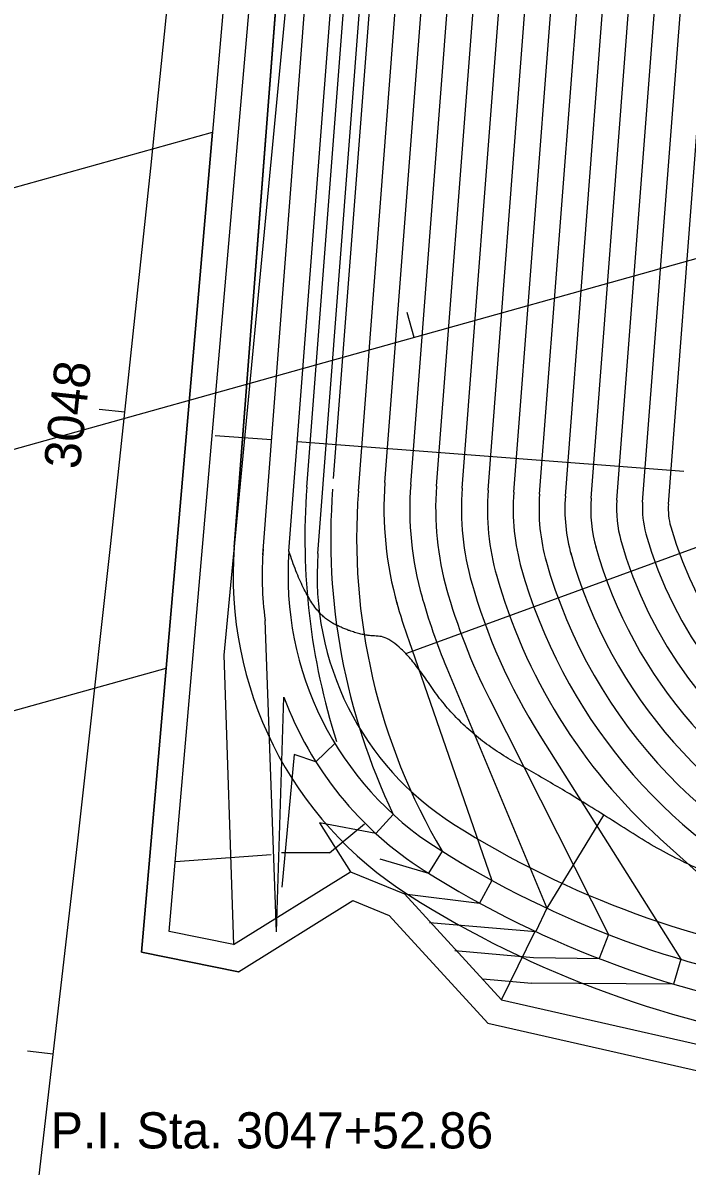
# Model space of a CAD drawing. Extents: x 1512289 to 1544686, y 552531 to 589211.
# Drawn here: x 1543224.9 to 1543276.3, y 587330.8 to 587419.3 of the extents above; entities that cross this region are included whole.
import ezdxf

# ---------------------------------------------------------------- set-up
doc = ezdxf.new("R2010")
doc.units = 0
for name, color, linetype in [('DR_P_Ditch', 7, 'Continuous'), ('DR_P_Erosion_Control', 7, 'Continuous'), ('DT_P_Break_Line', 7, 'Continuous'), ('DT_P_Contour_Major', 7, 'Continuous'), ('DT_P_Contour_Minor', 7, 'Continuous'), ('DT_P_Slope_Break_Line', 7, 'Continuous'), ('DT_P_TIN_Hull', 7, 'Continuous'), ('GE_X_CL_20', 7, 'Continuous'), ('GK_Visualization', 7, 'Continuous'), ('RW_P_Const_Limits', 7, 'Continuous'), ('SC_Scratch2', 7, 'Continuous')]:
    doc.layers.add(name, color=color, linetype=linetype)

msp = doc.modelspace()

# ---------------------------------------------------------------- linework, layer by layer
at = {"layer": 'DR_P_Ditch'}
for p, q in [((1543243.419, 587378.158), (1543246.948, 587424.142)), ((1543245.446, 587378.435), (1543248.942, 587423.989)), ((1543244.47, 587348.981), (1543243.593, 587373.077)), ((1543244.47, 587348.981), (1543245.06, 587367.128))]:
    msp.add_line(p, q, dxfattribs=at)
for centre, radius, start, end in [((1543270.373, 587376.522), 27, 175.61111, 187.3289), ((1543270.373, 587376.522), 25, 175.61111, 237.61296), ((1543270.373, 587376.522), 27, 200.36085, 237.61296), ((1543297.316, 587418.999), 75.302, 237.61296, 262.3082), ((1543297.316, 587418.999), 77.302, 237.61296, 262.3082)]:
    msp.add_arc(centre, radius, start, end, dxfattribs=at)
at = {"layer": 'DR_P_Erosion_Control'}
for p, q in [((1543241.209, 587378.76), (1543244.705, 587424.314)), ((1543244.705, 587424.314), (1543241.209, 587378.76)), ((1543247.69, 587378.263), (1543251.186, 587423.817)), ((1543247.69, 587378.263), (1543251.186, 587423.817))]:
    msp.add_line(p, q, dxfattribs=at)
for centre, radius, start, end in [((1543270.373, 587376.522), 29.25, 175.61111, 237.61296), ((1543270.373, 587376.522), 29.25, 175.61111, 237.61296), ((1543270.373, 587376.522), 22.75, 175.61111, 237.61296), ((1543270.373, 587376.522), 22.75, 175.61111, 237.61296), ((1543297.316, 587418.999), 73.052, 237.61296, 262.3082), ((1543297.316, 587418.999), 73.052, 237.61296, 262.3082), ((1543297.316, 587418.999), 79.552, 237.61296, 262.3082), ((1543297.316, 587418.999), 79.552, 237.61296, 262.3082)]:
    msp.add_arc(centre, radius, start, end, dxfattribs=at)
at = {"layer": 'DT_P_Break_Line'}
msp.add_line((1543241.154, 587347.996), (1543236.172, 587349), dxfattribs=at)
msp.add_lwpolyline([(1543241.154, 587347.996), (1543250.205, 587353.624), (1543254.38, 587351.91), (1543261.898, 587343.717), (1543284.879, 587338.499)], dxfattribs=at)
msp.add_open_spline([(1543307.516, 587355.279), (1543303.761, 587353.574), (1543297.723, 587353.574), (1543296.29, 587352.959), (1543290.972, 587350.957), (1543286.569, 587350.488), (1543276.224, 587353.875), (1543267.091, 587359.788), (1543258.853, 587364.356), (1543253.82, 587371.866), (1543250.743, 587371.866), (1543246.919, 587373.852), (1543245.446, 587378.435)], degree=2, dxfattribs=at)
at = {"layer": 'DT_P_Contour_Major'}
for p, q in [((1543252.876, 587383.764), (1543255.922, 587423.454)), ((1543262.846, 587382.999), (1543265.893, 587422.688)), ((1543272.817, 587382.234), (1543275.863, 587421.923)), ((1543254.71, 587371.511), (1543261.155, 587352.948)), ((1543261.155, 587352.948), (1543260.195, 587351.194)), ((1543254.38, 587351.91), (1543260.195, 587351.194))]:
    msp.add_line(p, q, dxfattribs=at)
for centre, radius, start, end in [((1543279.797, 587381.698), 27, 175.61111, 195.86297), ((1543279.797, 587381.698), 17, 175.61111, 195.86297), ((1543279.797, 587381.698), 7, 175.61111, 195.86297), ((1543303.222, 587388.354), 31.353, 195.86297, 279.22466), ((1543303.222, 587388.354), 41.353, 195.61111, 243.74464), ((1543303.222, 587388.354), 51.353, 195.61111, 199.14743)]:
    msp.add_arc(centre, radius, start, end, dxfattribs=at)
at = {"layer": 'DT_P_Contour_Minor'}
for p, q in [((1543247.421, 587443.908), (1543240.411, 587370.396)), ((1543246.829, 587383.384), (1543249.94, 587423.913)), ((1543248.887, 587384.07), (1543251.934, 587423.76)), ((1543250.817, 587383.078), (1543253.928, 587423.607)), ((1543254.87, 587383.611), (1543257.916, 587423.301)), ((1543256.864, 587383.458), (1543259.91, 587423.147)), ((1543258.858, 587383.305), (1543261.904, 587422.994)), ((1543260.852, 587383.152), (1543263.898, 587422.841)), ((1543264.841, 587382.846), (1543267.887, 587422.535)), ((1543266.835, 587382.693), (1543269.881, 587422.382)), ((1543268.829, 587382.54), (1543271.875, 587422.229)), ((1543270.823, 587382.387), (1543273.869, 587422.076)), ((1543274.811, 587382.08), (1543277.857, 587421.77)), ((1543240.411, 587370.396), (1543241.154, 587347.996)), ((1543257.658, 587369.391), (1543265.396, 587350.797)), ((1543260.954, 587367.006), (1543270.17, 587348.761)), ((1543264.85, 587364.179), (1543275.77, 587346.846)), ((1543249.007, 587363.541), (1543247.536, 587362.117)), ((1543245.848, 587362.686), (1543244.902, 587352.427)), ((1543247.536, 587362.117), (1543245.848, 587362.686)), ((1543253.519, 587358.056), (1543252.171, 587356.579)), ((1543252.171, 587356.579), (1543247.811, 587357.403)), ((1543247.811, 587357.403), (1543250.205, 587353.624)), ((1543274.166, 587356.18), (1543287.237, 587344.375)), ((1543257.301, 587355.209), (1543256.256, 587353.506)), ((1543252.484, 587354.614), (1543256.256, 587353.506)), ((1543265.396, 587350.797), (1543264.549, 587348.986)), ((1543256.334, 587349.687), (1543264.549, 587348.986)), ((1543270.17, 587348.761), (1543269.449, 587346.895)), ((1543258.293, 587347.512), (1543264.379, 587346.993)), ((1543264.379, 587346.993), (1543269.449, 587346.895)), ((1543275.77, 587346.846), (1543275.198, 587344.929)), ((1543260.451, 587345.321), (1543264.208, 587345)), ((1543275.198, 587344.929), (1543264.208, 587345))]:
    msp.add_line(p, q, dxfattribs=at)
for centre, radius, start, end in [((1543298.29, 587379.434), 51.613, 175.61111, 197.74433), ((1543298.29, 587379.434), 49.613, 175.61111, 205.52395), ((1543279.797, 587381.698), 25, 175.61111, 195.86297), ((1543279.797, 587381.698), 23, 175.61111, 195.86297), ((1543279.797, 587381.698), 21, 175.61111, 195.86297), ((1543298.29, 587379.434), 47.613, 175.61111, 210.58297), ((1543279.797, 587381.698), 19, 175.61111, 195.86297), ((1543279.797, 587381.698), 15, 175.61111, 195.86297), ((1543279.797, 587381.698), 13, 175.61111, 195.86297), ((1543279.797, 587381.698), 11, 175.61111, 195.86297), ((1543279.797, 587381.698), 9, 175.61111, 195.86297), ((1543279.797, 587381.698), 5, 175.61111, 195.86297), ((1543303.222, 587388.354), 29.353, 195.86297, 281.26542), ((1543303.222, 587388.354), 35.353, 195.61111, 246.82613), ((1543303.222, 587388.354), 33.353, 195.61111, 277.39562), ((1543303.222, 587388.354), 37.353, 195.61111, 247.2377), ((1543303.222, 587388.354), 39.353, 195.61111, 251.86284), ((1543303.222, 587388.354), 45.353, 195.61111, 212.21141), ((1543303.222, 587388.354), 43.353, 195.61111, 227.91501), ((1543303.222, 587388.354), 47.353, 195.61111, 206.79697), ((1543303.222, 587388.354), 49.353, 195.61111, 202.59672)]:
    msp.add_arc(centre, radius, start, end, dxfattribs=at)
at = {"layer": 'DT_P_Slope_Break_Line'}
for p, q in [((1543239.739, 587387.397), (1543244.092, 587387.086)), ((1543276.008, 587384.6), (1543246.096, 587386.896)), ((1543300.074, 587387.2), (1543254.538, 587370.504)), ((1543269.795, 587358.005), (1543265.396, 587350.797)), ((1543248.574, 587355.093), (1543251.295, 587357.32)), ((1543236.654, 587354.401), (1543244.073, 587354.945)), ((1543248.574, 587355.093), (1543244.865, 587355.093)), ((1543261.898, 587343.717), (1543264.464, 587348.957))]:
    msp.add_line(p, q, dxfattribs=at)
at = {"layer": 'DT_P_TIN_Hull'}
msp.add_line((1543236.172, 587349), (1543244.36, 587443.445), dxfattribs=at)
at = {"layer": 'GE_X_CL_20'}
for p, q in [((1541212.248, 586824.181), (1543339.287, 587418.505)), ((1543255.128, 587394.99), (1543254.59, 587396.916)), ((1543232.748, 587389.19), (1543230.759, 587389.403)), ((1543227.206, 587339.498), (1543225.22, 587339.728))]:
    msp.add_line(p, q, dxfattribs=at)
msp.add_arc((1537339.326, 588021.259), 5927.22, 346.145191, 0.622804, dxfattribs=at)
at = {"layer": 'GK_Visualization'}
msp.add_line((1541212.248, 586824.181), (1543339.287, 587418.505), dxfattribs=at)
msp.add_arc((1537339.326, 588021.259), 5927.22, 346.145191, 0.622804, dxfattribs=at)
msp.add_arc((1537339.326, 588021.259), 5927.22, 346.145191, 0.622804, dxfattribs=at)
at = {"layer": 'RW_P_Const_Limits'}
for p, q in [((1543242.438, 587444.431), (1543239.529, 587410.878)), ((1543197.741, 587399.202), (1543239.529, 587410.878)), ((1543193.549, 587357.537), (1543235.931, 587369.379)), ((1543234.025, 587347.393), (1543235.931, 587369.379)), ((1543241.536, 587345.879), (1543234.025, 587347.393))]:
    msp.add_line(p, q, dxfattribs=at)
msp.add_lwpolyline([(1543241.536, 587345.879), (1543250.392, 587351.386), (1543253.208, 587350.229), (1543260.847, 587341.905), (1543284.727, 587336.482), (1543293.027, 587337.086), (1543305.154, 587333.628), (1543310.652, 587332.808), (1543314.015, 587332.157), (1543316.943, 587344.26), (1543324.235, 587346.101), (1543326.778, 587340.98), (1543332.54, 587342.743), (1543322.869, 587377.272), (1543328.657, 587389.3), (1543334.306, 587391.77), (1543350.68, 587394.118)], dxfattribs=at)
at = {"layer": 'SC_Scratch2'}
for p, q in [((1543242.438, 587444.431), (1543239.529, 587410.878)), ((1543242.438, 587444.431), (1543239.529, 587410.878)), ((1543235.931, 587369.379), (1543239.529, 587410.878)), ((1543239.529, 587410.878), (1543235.931, 587369.379)), ((1543234.025, 587347.393), (1543235.931, 587369.379)), ((1543235.931, 587369.379), (1543234.025, 587347.393)), ((1543241.536, 587345.879), (1543234.025, 587347.393)), ((1543234.025, 587347.393), (1543241.536, 587345.879))]:
    msp.add_line(p, q, dxfattribs=at)
msp.add_lwpolyline([(1543241.536, 587345.879), (1543250.392, 587351.386), (1543253.208, 587350.229), (1543260.847, 587341.905), (1543284.727, 587336.482), (1543293.027, 587337.086), (1543305.154, 587333.628), (1543310.652, 587332.808), (1543314.156, 587332.111), (1543316.979, 587344.268), (1543324.259, 587346.101), (1543326.809, 587341.018), (1543332.602, 587342.686), (1543322.856, 587377.195), (1543328.657, 587389.3), (1543334.306, 587391.77), (1543350.68, 587394.118)], dxfattribs=at)

# ---------------------------------------------------------------- texts
at = {"layer": 'GE_X_CL_20'}
msp.add_text('3048', height=2.8, rotation=83.87843, dxfattribs=at).set_placement((1543229.251, 587384.721))
msp.add_text('P.I. Sta. 3047+52.86', height=2.8, dxfattribs=at).set_placement((1543227, 587332.2))

doc.saveas('drawing.dxf')
